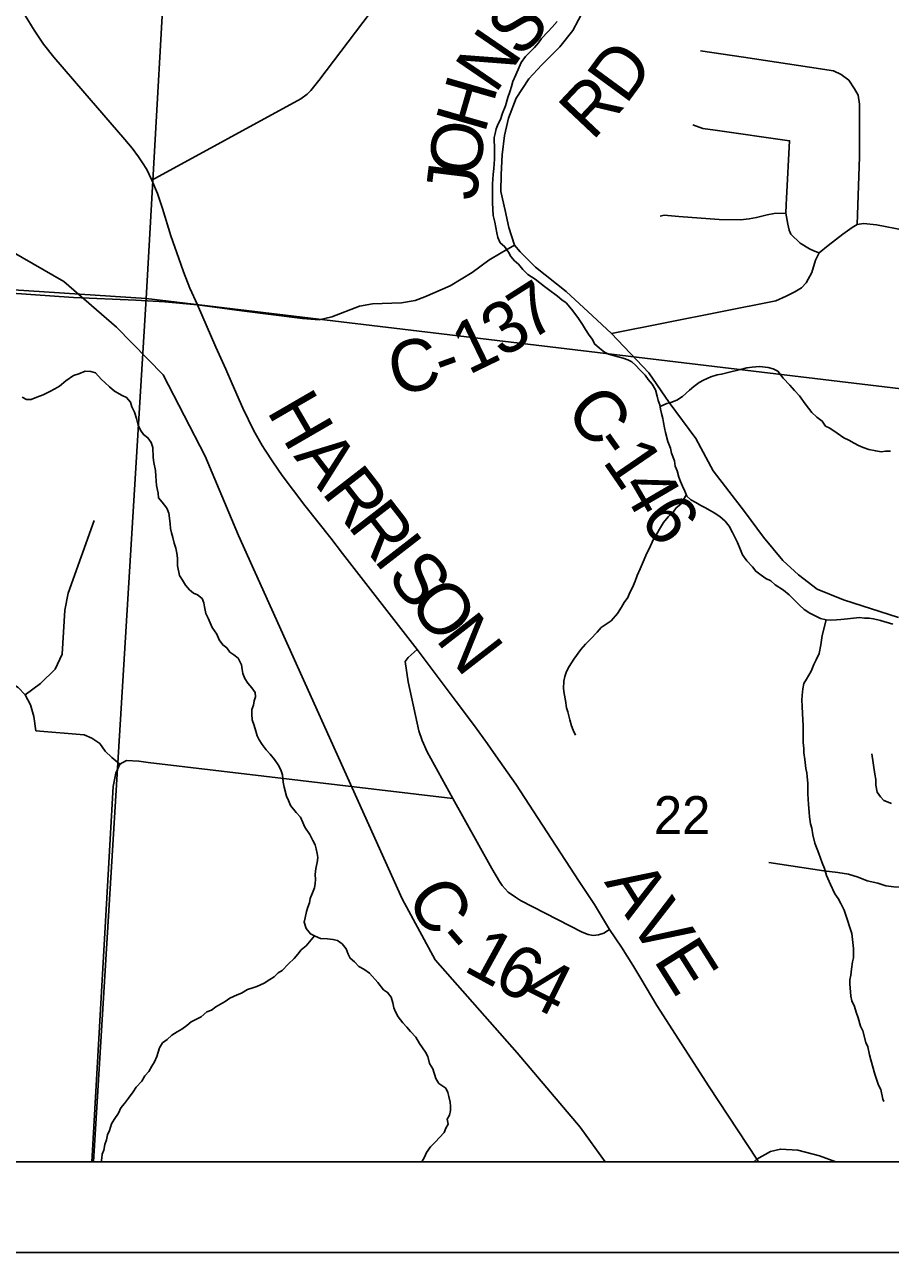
# Model space of a CAD drawing. Extents: x 0 to 34, y 0 to 22.
# Drawn here: x 7.016 to 7.97, y 14 to 15.353 of the extents above; entities that cross this region are included whole.
import ezdxf

# ---------------------------------------------------------------- set-up
doc = ezdxf.new("R2010")
doc.units = 0
for name, color, linetype in [('Default', 7, 'Continuous'), ('GM_X_County_Road', 7, 'Continuous'), ('GM_X_County_Road_Text', 7, 'Continuous'), ('GM_X_Minor_River', 7, 'Continuous'), ('GM_X_Rail_Line', 7, 'Continuous'), ('GM_X_Section', 7, 'Continuous'), ('GM_X_Section_Text', 7, 'Continuous'), ('GM_X_State_Route', 7, 'Continuous'), ('GM_X_Township_Road', 7, 'Continuous'), ('SH_Data', 7, 'Continuous')]:
    doc.layers.add(name, color=color, linetype=linetype)

msp = doc.modelspace()

# ---------------------------------------------------------------- linework, layer by layer
at = {"layer": 'Default'}
for points in [[(6.3691, 14.1), (7.0916, 14.1), (7.1496, 15.0512), (6.1715, 15.1151), (6.0802, 14.1319)], [(7.0916, 14.1), (8.0997, 14.1), (8.1869, 14.9268), (7.1496, 15.0512)]]:
    msp.add_lwpolyline(points, close=True, dxfattribs=at)
at = {"layer": 'GM_X_County_Road'}
for points in [[(7.6621, 15.4772), (7.6558, 15.4372), (7.646, 15.4022), (7.6324, 15.37), (7.6199, 15.3465), (7.6053, 15.3283), (7.5857, 15.3085), (7.5712, 15.293), (7.5572, 15.2718), (7.5489, 15.25), (7.5445, 15.2308), (7.5419, 15.2093), (7.5408, 15.1877), (7.5406, 15.1691), (7.5452, 15.1481), (7.5492, 15.1293), (7.5554, 15.1099)], [(7.0165, 15.3628), (7.0264, 15.3468), (7.0368, 15.3312), (7.0482, 15.3169), (7.0801, 15.2799), (7.1263, 15.2265), (7.1344, 15.2169), (7.1412, 15.2071)], [(7.1412, 15.2071), (7.1458, 15.2007), (7.1505, 15.1932), (7.156, 15.1816), (7.1622, 15.167), (7.1679, 15.1502), (7.1771, 15.1203), (7.188, 15.0888)], [(7.6624, 15.0126), (7.8435, 15.0486), (7.8547, 15.0538), (7.8644, 15.0583), (7.8718, 15.0627), (7.8768, 15.0684), (7.8831, 15.0798), (7.8871, 15.0935), (7.8912, 15.1014), (7.901, 15.1096), (7.9173, 15.1219), (7.9274, 15.1293), (7.9329, 15.1328), (7.9398, 15.1339), (7.9541, 15.1322), (8.0457, 15.1146), (8.2031, 15.0825)], [(7.5554, 15.1099), (7.5409, 15.1015), (7.5272, 15.0933), (7.5089, 15.0797), (7.4845, 15.065), (7.4569, 15.0529), (7.4459, 15.0488), (7.4309, 15.0462), (7.3992, 15.0454), (7.3848, 15.0427), (7.3543, 15.031), (7.3403, 15.0277), (7.3221, 15.0292), (7.2553, 15.0376), (7.2064, 15.044)], [(7.5554, 15.1099), (7.5616, 15.1024), (7.5788, 15.0855), (7.6125, 15.059), (7.6416, 15.0322), (7.6624, 15.0126), (7.7036, 14.9691), (7.726, 14.9365), (7.7551, 14.8968), (7.7744, 14.8613), (7.809, 14.8165), (7.8297, 14.7881), (7.8512, 14.7624), (7.8685, 14.7466), (7.8888, 14.7308), (7.918, 14.7192), (7.9784, 14.6998)], [(7.188, 15.0888), (7.1908, 15.0805), (7.1979, 15.0626), (7.2064, 15.044)], [(6.9074, 15.0636), (7.0696, 15.0521), (7.1382, 15.0492), (7.1704, 15.0476), (7.2064, 15.044)], [(7.2064, 15.044), (7.2266, 14.9974), (7.2375, 14.9734), (7.2444, 14.9571), (7.2564, 14.9304), (7.2682, 14.9053), (7.2777, 14.889)], [(7.2777, 14.889), (7.2807, 14.8839), (7.2891, 14.871), (7.2995, 14.8562), (7.3247, 14.8229), (7.353, 14.787), (7.3659, 14.7703), (7.4482, 14.6644), (7.4911, 14.607), (7.5114, 14.5803), (7.5258, 14.5603), (7.5349, 14.5473), (7.5569, 14.5159), (7.5864, 14.4707), (7.6269, 14.4086), (7.6436, 14.3833), (7.6603, 14.3559), (7.6732, 14.3364), (7.6857, 14.3165), (7.6945, 14.3017), (7.7124, 14.2721), (7.7699, 14.1826), (7.8224, 14.1028), (7.8244, 14.1)], [(7.4876, 14.5001), (7.4594, 14.5516), (7.4539, 14.5642), (7.45, 14.5749), (7.4483, 14.5833), (7.4385, 14.6287), (7.4352, 14.651), (7.4385, 14.6557), (7.4482, 14.6644)], [(7.0898, 14.1), (7.1134, 14.5133), (7.1165, 14.528), (7.1209, 14.5382), (7.1282, 14.542), (7.1416, 14.5415), (7.1519, 14.5399), (7.4876, 14.5001)], [(7.6603, 14.3559), (7.6538, 14.3517), (7.6479, 14.3499), (7.642, 14.3494), (7.6366, 14.3502), (7.63, 14.3528), (7.5621, 14.3877), (7.5565, 14.3913), (7.5485, 14.397), (7.542, 14.4043), (7.5389, 14.4086), (7.5304, 14.423), (7.4876, 14.5001)], [(7.8224, 14.1028), (7.8376, 14.1113), (7.8485, 14.1139), (7.8676, 14.1126), (7.8916, 14.1064), (7.9093, 14.1)]]:
    msp.add_lwpolyline(points, dxfattribs=at)
at = {"layer": 'GM_X_Minor_River'}
for points in [[(7.7551, 14.8262), (7.7499, 14.8294), (7.7455, 14.8334), (7.743, 14.8388), (7.7406, 14.8442), (7.7385, 14.8496), (7.7367, 14.8542), (7.7347, 14.8611), (7.7326, 14.8665), (7.7316, 14.8722), (7.7285, 14.8807), (7.7272, 14.8861), (7.7244, 14.8934), (7.7217, 14.9033), (7.7208, 14.9087), (7.7198, 14.9144), (7.7188, 14.919), (7.7175, 14.9244), (7.7165, 14.929), (7.7155, 14.9339), (7.7138, 14.9389), (7.7125, 14.9435), (7.7108, 14.9504), (7.7072, 14.9566), (7.7028, 14.9617), (7.6996, 14.9668), (7.6937, 14.9727), (7.6893, 14.9774), (7.6849, 14.9814), (7.6804, 14.9834), (7.6752, 14.9855), (7.6658, 14.9881), (7.659, 14.9898), (7.6545, 14.9919), (7.649, 14.9963), (7.6438, 15.001), (7.6413, 15.006), (7.6377, 15.0107), (7.6337, 15.0169), (7.6305, 15.0224), (7.6254, 15.0301), (7.6182, 15.0395), (7.6123, 15.0462), (7.6075, 15.0498), (7.6027, 15.0537), (7.5931, 15.0609), (7.5887, 15.0645), (7.5835, 15.0684), (7.5783, 15.0724), (7.5701, 15.0776), (7.5646, 15.0832), (7.5599, 15.089), (7.5555, 15.0926), (7.5514, 15.0973), (7.549, 15.1023), (7.5446, 15.1085), (7.5398, 15.1125), (7.537, 15.1183), (7.536, 15.1236), (7.5338, 15.1351), (7.5321, 15.1424), (7.5314, 15.1565), (7.5312, 15.1728), (7.5314, 15.1774), (7.5321, 15.1876), (7.5327, 15.1944), (7.5335, 15.2047), (7.5333, 15.2115), (7.5336, 15.2195), (7.533, 15.224), (7.5332, 15.2286), (7.5341, 15.2331), (7.5354, 15.238), (7.5375, 15.2436), (7.5399, 15.2485), (7.5424, 15.2552), (7.5454, 15.2635), (7.5483, 15.2725), (7.5504, 15.2789), (7.5522, 15.2849), (7.5535, 15.2902), (7.5568, 15.2977), (7.5605, 15.3059), (7.5629, 15.3111), (7.5677, 15.3178), (7.5732, 15.3233), (7.5776, 15.3277), (7.5819, 15.3329), (7.5851, 15.3377), (7.5926, 15.3454), (7.5969, 15.3502), (7.6025, 15.3565)], [(7.0131, 14.9423), (7.0179, 14.9398), (7.0229, 14.94), (7.0294, 14.9425), (7.0363, 14.9449), (7.0437, 14.9488), (7.0491, 14.9517), (7.0541, 14.9545), (7.0611, 14.9604), (7.0697, 14.9662), (7.0755, 14.9682), (7.0824, 14.971), (7.0888, 14.9708), (7.0941, 14.9691), (7.1003, 14.9621), (7.1047, 14.9581), (7.1095, 14.9538), (7.1147, 14.949), (7.1232, 14.9442), (7.1281, 14.9421), (7.1325, 14.937), (7.1338, 14.9317), (7.137, 14.9258), (7.1391, 14.9189), (7.1411, 14.9116), (7.1436, 14.9059), (7.1468, 14.9012), (7.1516, 14.8976), (7.1553, 14.8925), (7.157, 14.8868), (7.1573, 14.8761), (7.1583, 14.8704), (7.1599, 14.8616), (7.1604, 14.8555), (7.1612, 14.8452), (7.1628, 14.8368), (7.1634, 14.8315), (7.1674, 14.8268), (7.1725, 14.8201), (7.1746, 14.8147), (7.1755, 14.809), (7.1761, 14.8029), (7.1767, 14.7976), (7.1776, 14.793), (7.179, 14.7876), (7.1807, 14.7815), (7.1824, 14.7761), (7.1837, 14.7704), (7.1843, 14.765), (7.1844, 14.7567), (7.1863, 14.7459), (7.1899, 14.7409), (7.1931, 14.7351), (7.1975, 14.73), (7.2019, 14.7264), (7.2064, 14.7247), (7.2116, 14.7204), (7.2133, 14.7158), (7.2139, 14.7112), (7.2156, 14.7039), (7.2181, 14.6989), (7.2223, 14.6885), (7.2277, 14.6811), (7.2302, 14.6749), (7.2341, 14.6694), (7.2386, 14.6662), (7.2419, 14.6616), (7.2463, 14.6584), (7.2511, 14.6548)], [(7.7159, 14.9321), (7.7232, 14.9356), (7.7278, 14.9366), (7.7343, 14.939), (7.7405, 14.9433), (7.7484, 14.9503), (7.7531, 14.9543), (7.7589, 14.9587), (7.7636, 14.9612), (7.7716, 14.9647), (7.7789, 14.9671), (7.7835, 14.9677), (7.7908, 14.9697), (7.8046, 14.973), (7.8115, 14.9747), (7.8172, 14.9756), (7.8252, 14.9761), (7.835, 14.975), (7.8403, 14.9737), (7.8455, 14.9712), (7.8513, 14.9634), (7.8587, 14.9556), (7.8638, 14.9497), (7.8693, 14.9438), (7.8758, 14.9349), (7.8831, 14.9255), (7.8886, 14.9204), (7.8945, 14.916), (7.8981, 14.9105), (7.903, 14.9081), (7.9111, 14.9029), (7.9182, 14.8977), (7.9238, 14.8952), (7.9297, 14.8916), (7.9346, 14.8891), (7.9395, 14.8871), (7.9458, 14.8846), (7.9534, 14.8832), (7.9594, 14.8822), (7.964, 14.8828), (7.9697, 14.883)], [(7.7448, 14.835), (7.7387, 14.8245), (7.7337, 14.8205), (7.7301, 14.8157), (7.7246, 14.8105), (7.7198, 14.8042), (7.7154, 14.7968), (7.7114, 14.7905), (7.7086, 14.786), (7.704, 14.7752), (7.7008, 14.7699), (7.6983, 14.7636), (7.6941, 14.7531), (7.6905, 14.746), (7.6884, 14.7396), (7.6855, 14.7325), (7.6826, 14.7273), (7.6802, 14.7216), (7.6762, 14.7161), (7.6733, 14.7109), (7.6689, 14.7042), (7.6618, 14.6961), (7.6564, 14.6921), (7.6509, 14.6885), (7.6466, 14.6833), (7.6391, 14.6759), (7.6336, 14.6704), (7.6284, 14.6642), (7.6209, 14.6538), (7.6157, 14.6456), (7.6128, 14.64), (7.6111, 14.6347), (7.6098, 14.6295), (7.6095, 14.6215), (7.6101, 14.6158), (7.6117, 14.6081), (7.6129, 14.6001), (7.6143, 14.5955), (7.6163, 14.5867), (7.6183, 14.5802), (7.6201, 14.5755), (7.6227, 14.5701)], [(7.9722, 14.6922), (7.9587, 14.6964), (7.9508, 14.6982), (7.9463, 14.6988), (7.941, 14.6989), (7.9357, 14.6995), (7.9288, 14.699), (7.9223, 14.6981), (7.9151, 14.6976), (7.9101, 14.697), (7.9037, 14.6968), (7.8988, 14.697), (7.8924, 14.6987), (7.8808, 14.7044), (7.8745, 14.7085), (7.8693, 14.7132), (7.8631, 14.7195), (7.8579, 14.7246), (7.852, 14.7298), (7.8428, 14.7358), (7.838, 14.7401), (7.8324, 14.7426), (7.8272, 14.7462), (7.8212, 14.7506), (7.8176, 14.7556), (7.8114, 14.7619), (7.8067, 14.7686), (7.8046, 14.7743), (7.8011, 14.7821), (7.7958, 14.7933), (7.7918, 14.8002), (7.7875, 14.8057), (7.7816, 14.8108), (7.7756, 14.8148), (7.7659, 14.8205), (7.7607, 14.823), (7.7551, 14.8262)], [(7.899, 14.697), (7.8944, 14.6797), (7.8938, 14.6747), (7.8929, 14.6694), (7.891, 14.66), (7.8877, 14.6529), (7.8853, 14.6477), (7.8824, 14.6406), (7.8771, 14.6316), (7.8743, 14.6268), (7.873, 14.6211), (7.8723, 14.6135), (7.8722, 14.6086), (7.8723, 14.6018), (7.8728, 14.5934), (7.8733, 14.5873), (7.8735, 14.5804), (7.8736, 14.5725), (7.8736, 14.5618), (7.8741, 14.5553), (7.8743, 14.5504), (7.8752, 14.5431), (7.8764, 14.5332), (7.8774, 14.5286), (7.878, 14.524), (7.8785, 14.5172), (7.8787, 14.5126), (7.8785, 14.5054), (7.8792, 14.4936), (7.8801, 14.4852), (7.8806, 14.4799), (7.8815, 14.4722), (7.8829, 14.4676), (7.8841, 14.46), (7.8865, 14.4508), (7.8907, 14.4396), (7.8945, 14.4292), (7.8969, 14.4231), (7.8993, 14.4154), (7.9035, 14.4054), (7.9085, 14.3953), (7.9121, 14.3899), (7.9149, 14.3844), (7.9185, 14.3771), (7.9206, 14.3717), (7.9223, 14.366), (7.9247, 14.359), (7.9271, 14.3513), (7.928, 14.3449), (7.9288, 14.3349), (7.929, 14.3304), (7.9288, 14.3247), (7.9279, 14.3202), (7.9269, 14.3122), (7.9259, 14.3054), (7.925, 14.3005), (7.9248, 14.2959), (7.9259, 14.2822), (7.9272, 14.2772), (7.93, 14.2711), (7.9317, 14.2649), (7.9341, 14.2584), (7.9365, 14.2495), (7.9393, 14.2441), (7.9427, 14.2315), (7.9448, 14.2265), (7.9464, 14.2177), (7.9481, 14.2123), (7.9525, 14.1965), (7.9566, 14.1842), (7.9591, 14.1796), (7.9614, 14.1689), (7.9624, 14.1663)], [(7.2511, 14.6548), (7.2547, 14.6475), (7.2556, 14.6425), (7.2562, 14.6379), (7.2583, 14.6325), (7.2619, 14.6274), (7.2663, 14.622), (7.2699, 14.6169), (7.2702, 14.6123), (7.2689, 14.6078), (7.2679, 14.6029), (7.2663, 14.5984), (7.2661, 14.5931), (7.2666, 14.587), (7.2687, 14.5805), (7.2704, 14.5743), (7.2721, 14.5693), (7.2742, 14.5647), (7.2774, 14.5596), (7.2818, 14.5538), (7.2862, 14.5491), (7.2913, 14.5432), (7.2953, 14.5374), (7.2981, 14.5316), (7.2998, 14.5262), (7.3007, 14.5182), (7.3017, 14.5128), (7.3043, 14.5029), (7.3065, 14.4978), (7.3089, 14.4924), (7.3151, 14.4846), (7.3199, 14.4795), (7.3223, 14.4737), (7.3244, 14.4687), (7.3302, 14.4605), (7.3334, 14.454), (7.3359, 14.4493), (7.3369, 14.4447), (7.3382, 14.4397), (7.3388, 14.4352), (7.3383, 14.4295), (7.3365, 14.4231), (7.3359, 14.4163), (7.3361, 14.4109), (7.336, 14.4064), (7.335, 14.4019), (7.3329, 14.3962), (7.3304, 14.3899), (7.3295, 14.3853), (7.3278, 14.3804), (7.3265, 14.3755), (7.3248, 14.3688), (7.3239, 14.3639), (7.3259, 14.357), (7.3306, 14.3511), (7.3359, 14.3486), (7.3419, 14.3461), (7.3494, 14.3455), (7.3555, 14.3449), (7.3607, 14.3436), (7.3656, 14.34), (7.3699, 14.3345), (7.3724, 14.3287), (7.3745, 14.3241), (7.3793, 14.3201), (7.3841, 14.315), (7.3897, 14.3122), (7.3956, 14.3078), (7.4051, 14.2976), (7.4113, 14.2894), (7.4157, 14.2866), (7.4197, 14.2811), (7.4214, 14.275), (7.4227, 14.2696), (7.4245, 14.265), (7.4273, 14.2596), (7.4324, 14.2529), (7.4368, 14.2482), (7.4408, 14.2435), (7.4467, 14.2372), (7.451, 14.2303), (7.4575, 14.2205), (7.46, 14.2159), (7.462, 14.2082), (7.4656, 14.2024), (7.469, 14.1916), (7.4723, 14.1862), (7.4797, 14.181), (7.4822, 14.1763), (7.4832, 14.1718), (7.4848, 14.1656), (7.4851, 14.161), (7.4849, 14.1565), (7.484, 14.1512), (7.4815, 14.1467), (7.4825, 14.1414), (7.4797, 14.1369), (7.478, 14.132), (7.4729, 14.1265), (7.4685, 14.1217), (7.463, 14.1162)], [(7.3351, 14.349), (7.326, 14.3379), (7.3205, 14.3336), (7.317, 14.3288), (7.3126, 14.324), (7.3067, 14.3181), (7.2996, 14.3107), (7.295, 14.3082), (7.2907, 14.3038), (7.286, 14.3006), (7.2798, 14.2966), (7.2717, 14.2931), (7.2671, 14.2917), (7.2613, 14.2896), (7.2547, 14.2857), (7.2501, 14.2839), (7.242, 14.28), (7.2369, 14.2764), (7.2315, 14.2736), (7.2265, 14.2707), (7.2218, 14.2671), (7.2164, 14.265), (7.2105, 14.2595), (7.1993, 14.2542), (7.1946, 14.2501), (7.1892, 14.2462), (7.1838, 14.2429), (7.1779, 14.2393), (7.1728, 14.2346), (7.1678, 14.2309), (7.1646, 14.2253), (7.1629, 14.2208), (7.1616, 14.2159), (7.1591, 14.21), (7.1559, 14.2051), (7.1526, 14.1992), (7.1483, 14.1947), (7.1451, 14.1888), (7.1388, 14.1822), (7.1356, 14.1769), (7.1304, 14.1699), (7.126, 14.164), (7.1217, 14.1592), (7.1192, 14.1536), (7.1144, 14.1465), (7.1116, 14.1417), (7.1094, 14.1345), (7.1073, 14.1297), (7.106, 14.124), (7.1043, 14.1191), (7.103, 14.1127), (7.1013, 14.1082), (7.1008, 14.1037), (7.1003, 14.1)], [(7.463, 14.1162), (7.4586, 14.1103), (7.4565, 14.105), (7.4534, 14.1)]]:
    msp.add_lwpolyline(points, dxfattribs=at)
at = {"layer": 'GM_X_Rail_Line'}
msp.add_lwpolyline([(7.6553, 14.1), (7.6278, 14.1382), (7.5584, 14.2199), (7.4682, 14.3223), (7.4319, 14.3895), (7.2515, 14.7898), (7.2148, 14.8773), (7.1684, 14.967), (7.1172, 15.0196), (7.0591, 15.07), (6.9789, 15.1159)], dxfattribs=at)
at = {"layer": 'GM_X_Section'}
for points in [[(7.2064, 16.0507), (7.1496, 15.0512), (6.1715, 15.1151), (6.268, 16.1109)], [(7.2064, 16.0507), (8.2891, 15.9218), (8.1869, 14.9268), (7.1496, 15.0512)]]:
    msp.add_lwpolyline(points, close=True, dxfattribs=at)
at = {"layer": 'GM_X_State_Route'}
msp.add_lwpolyline([(5.2499, 15.926), (5.1715, 15.1469), (5.1456, 14.8898), (5.1035, 14.4713), (5.0661, 14.1), (8.9, 14.1), (8.9, 16.8616)], dxfattribs=at)
at = {"layer": 'GM_X_Township_Road'}
msp.add_line((7.819, 14.1), (7.8224, 14.1028), dxfattribs=at)
for points in [[(7.156, 15.1816), (7.3203, 15.2711), (7.327, 15.2762), (7.3312, 15.2804), (7.3398, 15.2914), (7.4044, 15.3767)], [(7.7605, 15.3242), (7.8078, 15.3171), (7.8803, 15.306), (7.907, 15.3019), (7.9153, 15.2979), (7.9238, 15.2916), (7.9302, 15.2823), (7.934, 15.275), (7.9357, 15.2653), (7.9355, 15.2073), (7.9329, 15.1328)], [(7.7521, 15.2425), (7.7629, 15.2383), (7.7765, 15.2365), (7.8586, 15.225), (7.8553, 15.1615), (7.8549, 15.1542), (7.8544, 15.1452), (7.8567, 15.133), (7.858, 15.1266), (7.86, 15.1219), (7.8702, 15.112), (7.8806, 15.1058), (7.8859, 15.1032), (7.8912, 15.1014)], [(7.7161, 15.1417), (7.7204, 15.143), (7.7364, 15.1414), (7.7811, 15.1381), (7.8045, 15.1379), (7.814, 15.139), (7.8221, 15.1405), (7.828, 15.1419), (7.834, 15.1432), (7.8414, 15.1446), (7.8544, 15.1452)], [(7.0164, 14.6145), (7.0333, 14.6269), (7.0496, 14.6427), (7.0571, 14.6593), (7.0601, 14.7078), (7.064, 14.7263), (7.0925, 14.8064)], [(7.1209, 14.5382), (7.1119, 14.5452), (7.1047, 14.5522), (7.0986, 14.5608), (7.09, 14.5668), (7.0814, 14.5704), (7.0283, 14.5749), (7.0261, 14.5904), (7.0225, 14.6034), (7.0164, 14.6145), (7.0086, 14.6225), (6.9975, 14.6297), (6.9751, 14.638), (6.964, 14.6424), (6.956, 14.6488), (6.9482, 14.6596), (6.9433, 14.6729), (6.9422, 14.6842), (6.945, 14.6969)], [(7.949, 14.5494), (7.9525, 14.5269), (7.9534, 14.5211), (7.9537, 14.5149), (7.955, 14.5072), (7.9588, 14.5019), (7.9622, 14.4978), (7.9709, 14.4945)], [(8.056, 14.4581), (8.0492, 14.3956), (8.042, 14.3942), (8.0325, 14.3962), (7.9881, 14.402), (7.9732, 14.4029), (7.9645, 14.4041), (7.9558, 14.4068), (7.9441, 14.4095), (7.9342, 14.4134), (7.9234, 14.4167), (7.9117, 14.4185), (7.8961, 14.4206), (7.8356, 14.4296)]]:
    msp.add_lwpolyline(points, dxfattribs=at)
at = {"layer": 'SH_Data'}
for p, q in [((2.1, 14.1), (8.9, 14.1)), ((2, 14), (9, 14))]:
    msp.add_line(p, q, dxfattribs=at)

# ---------------------------------------------------------------- texts
at = {"layer": 'GM_X_County_Road_Text'}
for s, height, rotation, p in [('S', 0.0568, 45.5636, (7.561, 15.3149)), ('N', 0.0568, 55.5941, (7.5344, 15.2757)), ('D', 0.0568, 53.7838, (7.6782, 15.2637)), ('H', 0.0568, 73.9145, (7.5226, 15.2319)), ('R', 0.0568, 46.6451, (7.6413, 15.224)), ('O', 0.0568, 82.6314, (7.5167, 15.1846)), ('J', 0.0568, 83.0283, (7.5134, 15.1582)), ('7', 0.0568, 32.5031, (7.5724, 15.0036)), ('3', 0.0568, 31.6331, (7.5418, 14.9847)), ('1', 0.0568, 25.775, (7.5047, 14.9665)), ('C', 0.0568, 12.4626, (7.4236, 14.9438)), ('-', 0.0568, 19.827, (7.4768, 14.9561)), ('H', 0.0568, 300.0983, (7.2819, 14.9272)), ('C', 0.0568, 308.7366, (7.6097, 14.9263)), ('-', 0.0568, 305.4304, (7.6384, 14.8906)), ('A', 0.0568, 307.5376, (7.3115, 14.8773)), ('1', 0.0568, 304.4536, (7.6517, 14.8718)), ('R', 0.0568, 307.7993, (7.3421, 14.8374)), ('4', 0.0568, 300.3029, (7.671, 14.8439)), ('R', 0.0568, 307.8, (7.3707, 14.8005)), ('6', 0.0568, 306.1592, (7.6921, 14.8084)), ('I', 0.0568, 307.7988, (7.3993, 14.7636)), ('S', 0.0568, 307.8044, (7.4136, 14.7452)), ('O', 0.0568, 307.801, (7.4371, 14.7149)), ('N', 0.0568, 307.8023, (7.4677, 14.6754)), ('C', 0.0568, 300.6958, (7.4352, 14.3917)), ('AVE', 0.05682, 302.2146, (7.6538, 14.4081)), ('-', 0.0568, 310.9021, (7.4655, 14.3426)), ('1', 0.0568, 331.2505, (7.4978, 14.3112)), ('6', 0.0568, 332.5993, (7.5298, 14.2937)), ('4', 0.0568, 333.6344, (7.5619, 14.2771))]:
    msp.add_text(s, height=height, rotation=rotation, dxfattribs=at).set_placement(p)
at = {"layer": 'GM_X_Section_Text'}
msp.add_text('22', height=0.04186, rotation=0, dxfattribs=at).set_placement((7.709, 14.4609))

doc.saveas('drawing.dxf')
